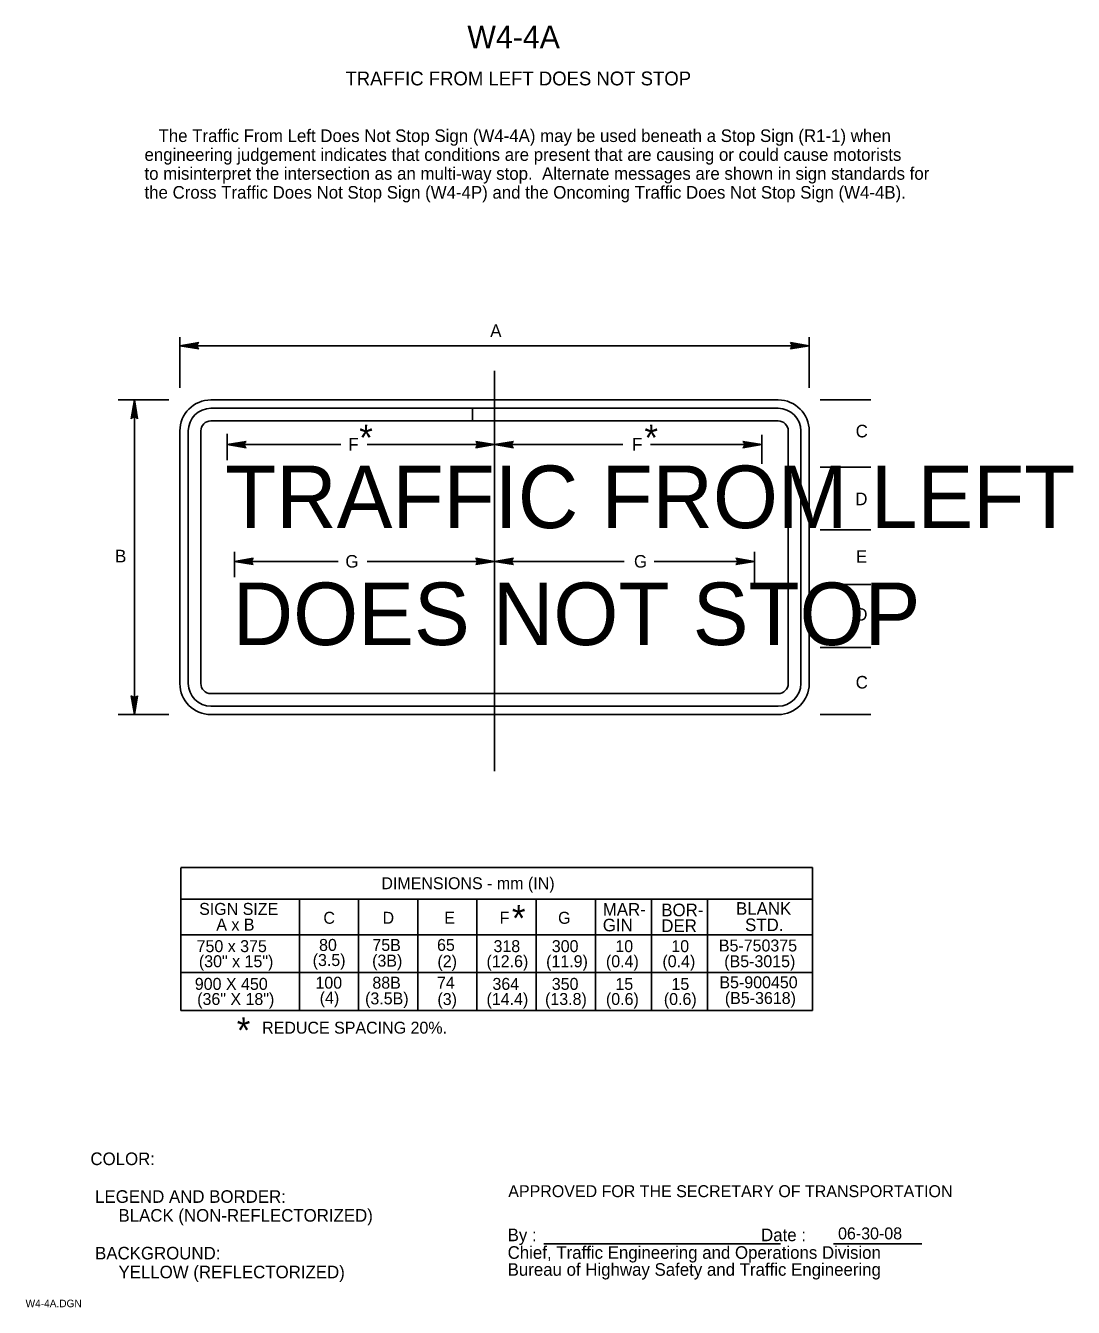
# Model space of a CAD drawing. Extents: x 0.013 to 0.221, y 0.004 to 0.259.
import ezdxf

# ---------------------------------------------------------------- set-up
doc = ezdxf.new("R2010")
doc.units = 0
for name, color, linetype in [('1', 7, 'Continuous'), ('2', 7, 'Continuous'), ('3', 7, 'Continuous')]:
    doc.layers.add(name, color=color, linetype=linetype)

# ---------------------------------------------------------------- blocks, each defined once
blk = doc.blocks.new('RARROW')
at = {"layer": '3'}
for p, q in [((-2.156, 0.285), (-2.2665, 0.384625)), ((-2.2665, 0.384625), (0, 0)), ((0, 0), (-2.2665, -0.379125)), ((-2.156, 0.285), (-2.075625, 0.12075)), ((0, 0), (-2.156, 0.285)), ((-2.14975, -0.2705), (0, 0)), ((-2.075625, 0.12075), (0, 0)), ((0, 0), (-2.074, -0.108)), ((-2.2665, -0.379125), (-2.14975, -0.2705)), ((-2.074, -0.108), (-2.14975, -0.2705))]:
    blk.add_line(p, q, dxfattribs=at)

msp = doc.modelspace()

# ---------------------------------------------------------------- linework, layer by layer
at = {"layer": '1'}
for p, q in [((0.10565, 0.11086), (0.10565, 0.19039)), ((0.0341, 0.12213), (0.0341, 0.18463)), ((0.10127, 0.18297), (0.04931, 0.18297)), ((0.10127, 0.18047), (0.10127, 0.18297)), ((0.16198, 0.18297), (0.10127, 0.18297)), ((0.10127, 0.18297), (0.10127, 0.18047)), ((0.04481, 0.17847), (0.04481, 0.1283)), ((0.04731, 0.1283), (0.04731, 0.17847)), ((0.04931, 0.18047), (0.10127, 0.18047)), ((0.10127, 0.18047), (0.16198, 0.18047)), ((0.16398, 0.17847), (0.16398, 0.1283)), ((0.16648, 0.1283), (0.16648, 0.17847)), ((0.05256, 0.17266), (0.05256, 0.17793)), ((0.10565, 0.17326), (0.10565, 0.17793)), ((0.15873, 0.17194), (0.15873, 0.17769)), ((0.05398, 0.14943), (0.05398, 0.15446)), ((0.10565, 0.15098), (0.10565, 0.1541)), ((0.15731, 0.14823), (0.15731, 0.15446)), ((0.16198, 0.1263), (0.04931, 0.1263)), ((0.04931, 0.1238), (0.16198, 0.1238)), ((0.11544, 0.01695), (0.16242, 0.01695)), ((0.17295, 0.01695), (0.1905, 0.01695))]:
    msp.add_line(p, q, dxfattribs=at)
for centre, radius, start, end in [((0.04931, 0.17847), 0.00617, 90, 180), ((0.16198, 0.17847), 0.00617, 360, 90), ((0.04931, 0.17847), 0.0045, 90, 180), ((0.16198, 0.17847), 0.0045, 0, 90), ((0.04931, 0.17847), 0.002, 90, 180), ((0.16198, 0.17847), 0.002, 0, 90), ((0.04931, 0.1283), 0.00617, 180, 270), ((0.04931, 0.1283), 0.0045, 180, 270), ((0.04931, 0.1283), 0.002, 180, 270), ((0.16198, 0.1283), 0.00617, 270, 0), ((0.16198, 0.1283), 0.0045, 270, 0), ((0.16198, 0.1283), 0.002, 270, 0)]:
    msp.add_arc(centre, radius, start, end, dxfattribs=at)
at = {"layer": '3'}
for p, q in [((0.04315, 0.18704), (0.04315, 0.1971)), ((0.16815, 0.18704), (0.16815, 0.1971)), ((0.16815, 0.19541), (0.04315, 0.19541)), ((0.04098, 0.18463), (0.03092, 0.18463)), ((0.04931, 0.18463), (0.16198, 0.18463)), ((0.17031, 0.18463), (0.18037, 0.18463)), ((0.04315, 0.17847), (0.04315, 0.1283)), ((0.16815, 0.17847), (0.16815, 0.1283)), ((0.07509, 0.17577), (0.05256, 0.17577)), ((0.10565, 0.17577), (0.08036, 0.17577)), ((0.10565, 0.17577), (0.13114, 0.17577)), ((0.13665, 0.17577), (0.15873, 0.17577)), ((0.17031, 0.1713), (0.18037, 0.1713)), ((0.17031, 0.1588), (0.18037, 0.1588)), ((0.07461, 0.15254), (0.05398, 0.15254)), ((0.10565, 0.15254), (0.08036, 0.15254)), ((0.10565, 0.15254), (0.13138, 0.15254)), ((0.13737, 0.15254), (0.15731, 0.15254)), ((0.17031, 0.14796), (0.18037, 0.14796)), ((0.17031, 0.13546), (0.18037, 0.13546)), ((0.04098, 0.12213), (0.03092, 0.12213)), ((0.04931, 0.12213), (0.16198, 0.12213)), ((0.17031, 0.12213), (0.18037, 0.12213)), ((0.04333, 0.09173), (0.16877, 0.09173)), ((0.04333, 0.09168), (0.04333, 0.06336)), ((0.16877, 0.09173), (0.16877, 0.06336)), ((0.16877, 0.08548), (0.04333, 0.08548)), ((0.0669, 0.08548), (0.0669, 0.06336)), ((0.07865, 0.08543), (0.07865, 0.06336)), ((0.0904, 0.08543), (0.0904, 0.06336)), ((0.10215, 0.08543), (0.10215, 0.06336)), ((0.1139, 0.08543), (0.1139, 0.06336)), ((0.12571, 0.08548), (0.12571, 0.06336)), ((0.13684, 0.08548), (0.13684, 0.06336)), ((0.14796, 0.08548), (0.14796, 0.06336)), ((0.04333, 0.07836), (0.16877, 0.07836)), ((0.04333, 0.07086), (0.16877, 0.07086)), ((0.04333, 0.06336), (0.16877, 0.06336))]:
    msp.add_line(p, q, dxfattribs=at)

# ---------------------------------------------------------------- block references
at = {"layer": '3', "xscale": 0.0016545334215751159}
for p, yscale, rotation in [((0.04315, 0.19541), -0.0016366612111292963, -180), ((0.0341, 0.18463), -0.0016366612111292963, 90), ((0.05256, 0.17577), -0.0016366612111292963, -180), ((0.10565, 0.17577), -0.0016366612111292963, -180), ((0.05398, 0.15254), -0.0016366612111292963, -180), ((0.10565, 0.15254), -0.0016366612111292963, -180), ((0.0341, 0.12213), 0.0016366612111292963, -90)]:
    msp.add_blockref('RARROW', p, dxfattribs=dict(at, yscale=yscale, rotation=rotation))
at = {"layer": '3', "xscale": 0.0016545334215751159, "yscale": 0.0016366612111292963}
for p in [(0.16815, 0.19541), (0.10565, 0.17577), (0.15873, 0.17577), (0.10565, 0.15254), (0.15731, 0.15254)]:
    msp.add_blockref('RARROW', p, dxfattribs=at)

# ---------------------------------------------------------------- texts
at = {"layer": '1'}
for s, height, p in [('W4-4A', 0.0045, (0.10024, 0.2545)), ('TRAFFIC FROM LEFT DOES NOT STOP', 0.0027503, (0.07603, 0.24713)), ('COLOR:', 0.0025, (0.02538, 0.03262)), ('APPROVED FOR THE SECRETARY OF TRANSPORTATION', 0.0023752, (0.10837, 0.02625)), (' LEGEND AND BORDER:', 0.0024998, (0.02538, 0.02512)), ('      BLACK (NON-REFLECTORIZED)', 0.0024998, (0.02538, 0.02138)), ('By :                                                Date :', 0.0024998, (0.10825, 0.0175)), (' BACKGROUND:', 0.0024998, (0.02538, 0.01388)), ('Chief, Traffic Engineering and Operations Division', 0.0024998, (0.10825, 0.014)), ('      YELLOW (REFLECTORIZED)', 0.0024998, (0.02538, 0.01013)), ('Bureau of Highway Safety and Traffic Engineering', 0.0024998, (0.10825, 0.01063)), ('W4-4A.DGN', 0.0015, (0.0125, 0.00438))]:
    msp.add_text(s, height=height, dxfattribs=at).set_placement(p)
at = {"layer": '2'}
for s, height, p in [('   The Traffic From Left Does Not Stop Sign (W4-4A) may be used beneath a Stop Sign (R1-1) when', 0.0024998, (0.03612, 0.23588)), ('engineering judgement indicates that conditions are present that are causing or could cause motorists', 0.00249975, (0.03612, 0.23213)), ('to misinterpret the intersection as an multi-way stop.  Alternate messages are shown in sign standards for', 0.00249975, (0.03612, 0.22838)), ('the Cross Traffic Does Not Stop Sign (W4-4P) and the Oncoming Traffic Does Not Stop Sign (W4-4B).', 0.0024998, (0.03612, 0.22463))]:
    msp.add_text(s, height=height, dxfattribs=at).set_placement(p)
at = {"layer": '3'}
for s, height, p in [('A', 0.0025, (0.10479, 0.19716)), ('*', 0.00518, (0.07877, 0.17455)), ('C', 0.0025, (0.17738, 0.1772)), ('F', 0.0025, (0.13297, 0.17456)), ('TRAFFIC FROM LEFT', 0.01242, (0.05215, 0.15917)), ('B', 0.0025, (0.03028, 0.15237)), ('G', 0.0025, (0.13334, 0.15132)), ('DOES NOT STOP', 0.01242, (0.05365, 0.13593)), ('DIMENSIONS - mm (IN)', 0.0023752, (0.08317, 0.08743)), ('SIGN SIZE', 0.002375, (0.04697, 0.08233)), ('MAR-', 0.0025, (0.12715, 0.08218)), ('BOR-', 0.0025, (0.13877, 0.08206)), ('BLANK', 0.0025, (0.15361, 0.08236)), ('A x B', 0.002375, (0.05038, 0.07921)), ('C', 0.00238, (0.07165, 0.08056)), ('D', 0.00238, (0.0834, 0.08056)), ('E', 0.00238, (0.09565, 0.08056)), ('F', 0.00238, (0.10665, 0.08056)), ('G', 0.00238, (0.11827, 0.08056)), ('GIN', 0.0025, (0.12715, 0.07906)), ('STD.', 0.0025, (0.15541, 0.07911)), ('DER', 0.0025, (0.13877, 0.07893)), ('750 x 375', 0.002375, (0.04647, 0.07493)), ('80', 0.002375, (0.07079, 0.07517)), ('75B', 0.002375, (0.08138, 0.07517)), ('65', 0.002375, (0.09422, 0.07517)), ('318', 0.002375, (0.10544, 0.07493)), ('300', 0.002375, (0.11702, 0.07493)), ('10', 0.002375, (0.12964, 0.07493)), ('10', 0.002375, (0.14076, 0.07493)), ('B5-750375', 0.002375, (0.1502, 0.07506)), ('(30" x 15")', 0.0023752, (0.04692, 0.07193)), ('(3.5)', 0.002375, (0.06952, 0.07217)), ('(3B)', 0.002375, (0.08133, 0.07205)), ('(2)', 0.002375, (0.0943, 0.07192)), ('(12.6)', 0.002375, (0.10405, 0.07193)), ('(11.9)', 0.002375, (0.11589, 0.07193)), ('(0.4)', 0.002375, (0.12777, 0.07193)), ('(B5-3015)', 0.002375, (0.15127, 0.07193)), ('900 X 450', 0.002375, (0.04611, 0.06743)), ('100', 0.002375, (0.07007, 0.06767)), ('88B', 0.002375, (0.08138, 0.06767)), ('74', 0.002375, (0.09421, 0.06767)), ('364', 0.002375, (0.10523, 0.06743)), ('350', 0.002375, (0.11702, 0.06743)), ('15', 0.002375, (0.12965, 0.06743)), ('B5-900450', 0.002375, (0.15031, 0.06775)), ('(36" X 18")', 0.0023752, (0.04658, 0.06443)), ('(4)', 0.002375, (0.07092, 0.06467)), ('(3.5B)', 0.002375, (0.07993, 0.06455)), ('(3)', 0.002375, (0.0943, 0.06442)), ('(14.4)', 0.002375, (0.10405, 0.06443)), ('(13.8)', 0.002375, (0.11568, 0.06443)), ('(0.6)', 0.002375, (0.12777, 0.06443)), ('(B5-3618)', 0.002375, (0.15139, 0.06463)), ('REDUCE SPACING 20%.', 0.0023752, (0.05949, 0.05873)), ('06-30-08', 0.002375, (0.17388, 0.01786))]:
    msp.add_text(s, height=height, dxfattribs=at).set_placement(p)
for s, height, p in [('*', 0.00518, (0.13542, 0.17455)), ('F', 0.0025, (0.07661, 0.17456)), ('D', 0.0025, (0.1773, 0.16372)), ('G', 0.0025, (0.07602, 0.15132)), ('E', 0.0025, (0.17744, 0.15228)), ('D', 0.0025, (0.1773, 0.14078)), ('C', 0.0025, (0.17738, 0.1273)), ('*', 0.00518, (0.10909, 0.0791)), ('(0.4)', 0.002375, (0.13899, 0.07193)), ('15', 0.002375, (0.14079, 0.06743)), ('(0.6)', 0.002375, (0.13927, 0.06443)), ('*', 0.00518, (0.05444, 0.05682))]:
    msp.add_text(s, height=height, rotation=360, dxfattribs=at).set_placement(p)

doc.saveas('drawing.dxf')
